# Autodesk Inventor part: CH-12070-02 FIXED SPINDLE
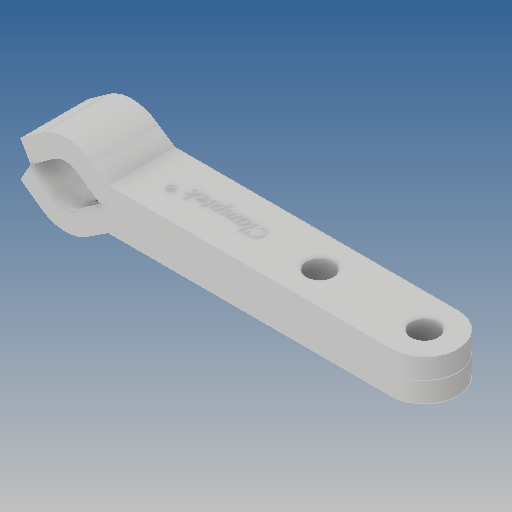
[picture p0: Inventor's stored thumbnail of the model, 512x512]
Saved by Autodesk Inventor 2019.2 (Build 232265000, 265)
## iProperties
Created: 2015-08
Part Number: CH-12070-02 FIXED SPINDLE
Material: Ogólny
Document SubType Name: Modeling
Designer: CADENGINEERING4
Density: 1 g/cm^3
Appearance: Domyślna
Author: CADENGINEERING4
Revision Number: ÈÎºÎ
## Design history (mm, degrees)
feature "ÇÐ³ý-À­Éì2"
feature "ÇÐ³ý-À­Éì5"
node "Bryła1"
node "Bryła2"
